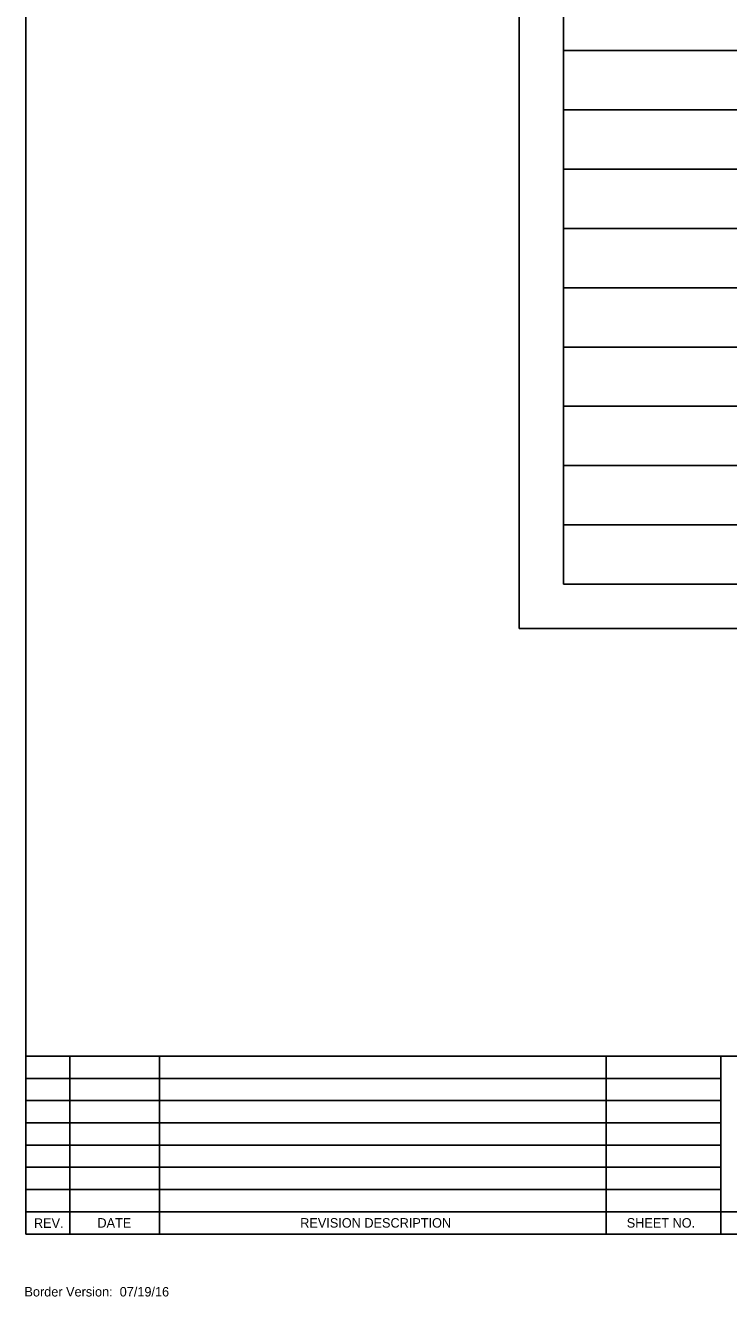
# Model space of a CAD drawing. Extents: x 0 to 31.8, y -0.5 to 20.8.
# Drawn here: x 0 to 5.92, y -0.53 to 10.19 of the extents above; entities that cross this region are included whole.
import ezdxf

# ---------------------------------------------------------------- set-up
doc = ezdxf.new("R2010")
doc.units = 0
for name, color, linetype in [('CT_Border_Perimeter_Shape', 7, 'Continuous'), ('CT_Locked', 7, 'Continuous'), ('CT_Title_Block_Linework', 7, 'Continuous'), ('CT_Title_Block_Text', 7, 'Continuous'), ('CT_TSH_Line_Work_Major', 7, 'Continuous'), ('CT_TSH_Line_Work_Minor', 7, 'Continuous')]:
    doc.layers.add(name, color=color, linetype=linetype)

msp = doc.modelspace()

# ---------------------------------------------------------------- linework, layer by layer
at = {"layer": 'CT_Border_Perimeter_Shape'}
msp.add_lwpolyline([(0, 0), (31.75, 0), (31.75, 20.75), (0, 20.75)], close=True, dxfattribs=at)
at = {"layer": 'CT_Locked'}
msp.add_line((0, 0), (0, 0), dxfattribs=at)
at = {"layer": 'CT_Title_Block_Linework'}
for p, q in [((31.75, 1.5), (0, 1.5)), ((0.37, 1.5), (0.37, 0)), ((1.125, 1.5), (1.125, 0)), ((4.89, 1.5), (4.89, 0)), ((5.858, 1.5), (5.858, 0)), ((5.858, 1.313), (0, 1.313)), ((5.858, 1.125), (0, 1.125)), ((5.858, 0.938), (0, 0.938)), ((5.858, 0.75), (0, 0.75)), ((5.858, 0.563), (0, 0.563)), ((5.858, 0.375), (0, 0.375)), ((8.614, 0.188), (0, 0.188))]:
    msp.add_line(p, q, dxfattribs=at)
at = {"layer": 'CT_TSH_Line_Work_Major'}
for p, q in [((4.156, 5.107), (4.156, 16.357)), ((24.156, 5.107), (4.156, 5.107))]:
    msp.add_line(p, q, dxfattribs=at)
at = {"layer": 'CT_TSH_Line_Work_Minor'}
for p, q in [((4.531, 15.982), (4.531, 5.482)), ((4.531, 9.982), (14.156, 9.982)), ((4.531, 9.482), (14.156, 9.482)), ((4.531, 8.982), (14.156, 8.982)), ((4.531, 8.482), (14.156, 8.482)), ((4.531, 7.982), (14.156, 7.982)), ((4.531, 7.482), (14.156, 7.482)), ((4.531, 6.982), (14.156, 6.982)), ((4.531, 6.482), (14.156, 6.482)), ((4.531, 5.982), (14.156, 5.982)), ((4.531, 5.482), (14.156, 5.482))]:
    msp.add_line(p, q, dxfattribs=at)

# ---------------------------------------------------------------- texts
at = {"layer": 'CT_Title_Block_Text'}
for s, p in [('REV.', (0.068, 0.052)), ('DATE', (0.603, 0.054)), ('REVISION DESCRIPTION', (2.312, 0.054)), ('SHEET NO.', (5.064, 0.054)), ('Border Version:  07/19/16', (-0.012, -0.527))]:
    msp.add_text(s, height=0.08, rotation=360, dxfattribs=at).set_placement(p)

doc.saveas('drawing.dxf')
